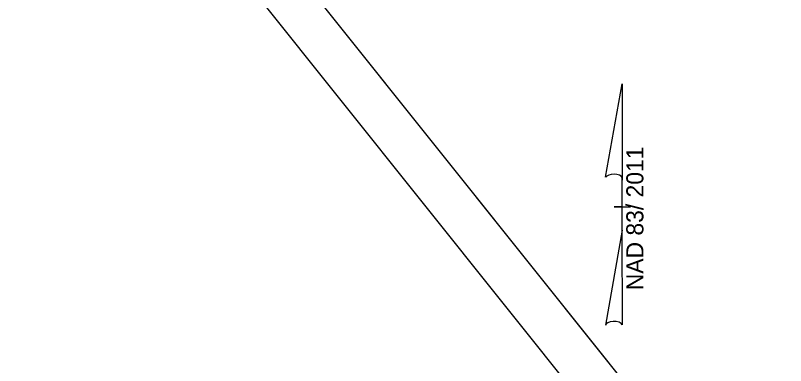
# Model space of a CAD drawing. Extents: x 473437 to 475344, y 504319 to 506318.
# Drawn here: x 473437.4 to 473820.6, y 505299.2 to 505473.2 of the extents above; entities that cross this region are included whole.
import ezdxf

# ---------------------------------------------------------------- set-up
doc = ezdxf.new("R2010")
doc.units = 0
for name, color, linetype in [('Prop North Arrow NAD83 for Plan Sheets CELL', 7, 'Continuous'), ('Sheet Clip Boundary CELL', 7, 'Continuous'), ('Sheet Plan CELL', 7, 'Continuous'), ('Sheet Plot Border Outside CELL', 7, 'Continuous')]:
    doc.layers.add(name, color=color, linetype=linetype)

msp = doc.modelspace()

# ---------------------------------------------------------------- linework, layer by layer
at = {"layer": 'Prop North Arrow NAD83 for Plan Sheets CELL'}
for p, q in [((473731.07, 505392.85), (473739.27, 505439.2)), ((473739.32, 505439.2), (473739.27, 505439.2)), ((473739.32, 505439.2), (473739.27, 505439.2)), ((473739.32, 505439.2), (473739.32, 505391.4)), ((473739.32, 505366.6), (473739.32, 505392.8)), ((473739.32, 505391.4), (473739.32, 505392.75)), ((473735.32, 505378.2), (473735.27, 505378.2)), ((473738.87, 505378.2), (473735.32, 505378.2)), ((473735.37, 505378.2), (473743.37, 505378.2)), ((473739.32, 505366.6), (473730.97, 505319.35)), ((473739.37, 505319.55), (473739.32, 505366.6))]:
    msp.add_line(p, q, dxfattribs=at)
for centre, start_param, end_param in [((473735.21, 505392.35), 0.216388, 2.908219), ((473735.21, 505319.18), 0.201328, 3.141593)]:
    msp.add_ellipse(centre, major_axis=(4.23, -0.03), ratio=0.461098, start_param=start_param, end_param=end_param, dxfattribs=at)
at = {"layer": 'Sheet Clip Boundary CELL'}
msp.add_lwpolyline([(473726.06, 505586.42), (473590.56, 505477.98), (474216.19, 504696.26), (474256.15, 504661.57), (474721.23, 504717.86), (474850.21, 504821.06), (475222.63, 505119.12), (474407.1, 506139.11), (474332.49, 506089.63), (474296.32, 506065.24), (474178.01, 505990.66), (474151.65, 505998.17), (473818.14, 505733.37), (473690.29, 505631.86)], close=True, dxfattribs=at)
at = {"layer": 'Sheet Plan CELL'}
msp.add_lwpolyline([(473465.55, 505634.17), (474402.85, 504463.03), (475222.63, 505119.12), (474285.35, 506290.25)], close=True, dxfattribs=at)
at = {"layer": 'Sheet Plot Border Outside CELL'}
msp.add_lwpolyline([(475344.24, 505003.2), (474292.3, 506317.59), (473437.39, 505633.37), (474489.32, 504318.99)], close=True, dxfattribs=at)

# ---------------------------------------------------------------- texts
at = {"layer": 'Prop North Arrow NAD83 for Plan Sheets CELL'}
msp.add_text('NAD 83/ 2011', height=8.5, rotation=90, dxfattribs=at).set_placement((473749.84, 505336.68))

doc.saveas('drawing.dxf')
